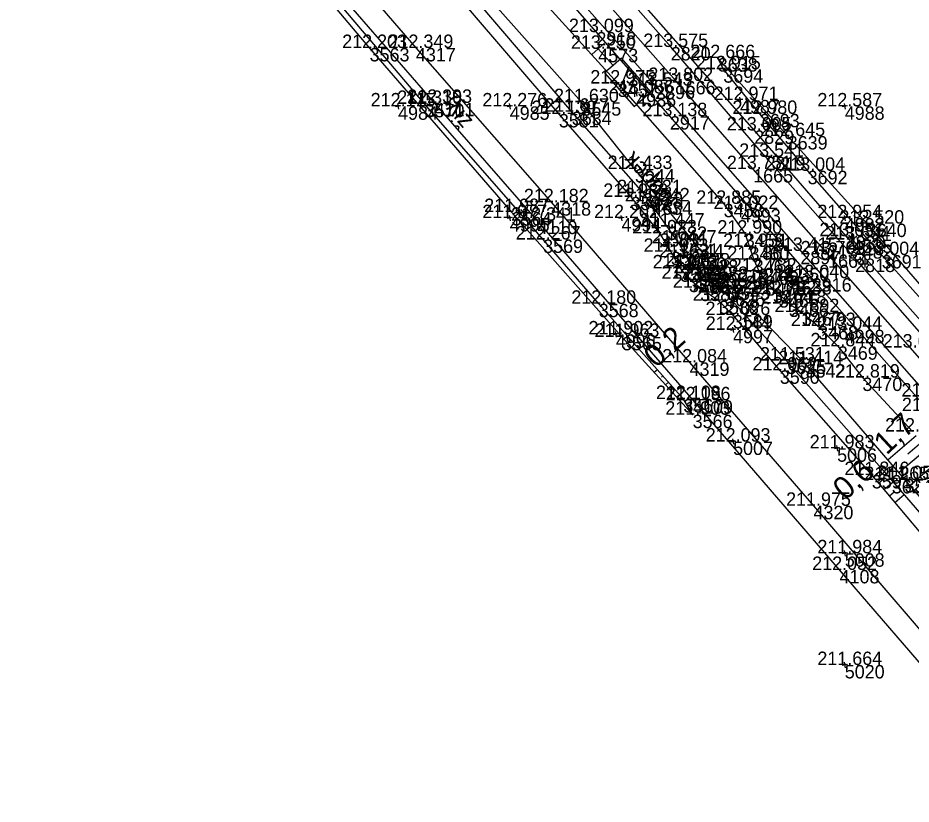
# Model space of a CAD drawing. Extents: x -556590 to -554855, y -1137918 to -1135717.
# Drawn here: x -555704 to -555624.1, y -1136522.5 to -1136452.1 of the extents above; entities that cross this region are included whole.
import ezdxf

# ---------------------------------------------------------------- set-up
doc = ezdxf.new("R2010")
doc.units = 0
for name, color, linetype in [('Vrstva 1', 7, 'Continuous'), ('Vrstva 4', 7, 'Continuous'), ('Vrstva 48', 7, 'Continuous'), ('Vrstva 49', 7, 'Continuous'), ('Vrstva 50', 7, 'Continuous'), ('Vrstva 51', 7, 'Continuous'), ('Vrstva 60', 7, 'Continuous'), ('Vrstva 61', 7, 'Continuous'), ('Vrstva 7', 7, 'Continuous')]:
    doc.layers.add(name, color=color, linetype=linetype)

msp = doc.modelspace()

# ---------------------------------------------------------------- linework, layer by layer
at = {"layer": 'Vrstva 1'}
msp.add_lwpolyline([(-555617.047, -1136489.655), (-555624.151, -1136481.584), (-555631.492, -1136473.245), (-555638.201, -1136465.612), (-555645.14, -1136457.724), (-555652.139, -1136449.756), (-555658.441, -1136442.59), (-555664.747, -1136435.415), (-555670.993, -1136428.307), (-555677.463, -1136420.947), (-555683.552, -1136414.017), (-555690.44, -1136406.179)], dxfattribs=at)
at = {"layer": 'Vrstva 4'}
for points in [[(-555622.431, -1136487.275), (-555632.955, -1136475.376), (-555645.659, -1136460.876), (-555652.243, -1136453.349), (-555664.779, -1136439.038), (-555675.055, -1136427.452), (-555687.678, -1136412.993), (-555700.952, -1136397.803)], [(-555697.757, -1136400.334), (-555685.919, -1136413.799), (-555674.147, -1136427.201), (-555663.818, -1136438.907), (-555656.688, -1136447.108), (-555646.98, -1136458.141), (-555633.977, -1136472.931), (-555622.465, -1136485.967)], [(-555620.12, -1136483.808), (-555629.064, -1136473.626), (-555637.092, -1136464.514), (-555645.582, -1136454.683), (-555654.149, -1136444.941), (-555659.148, -1136439.478), (-555660.228, -1136437.983), (-555660.506, -1136437.427), (-555660.012, -1136437.729), (-555658.962, -1136438.799), (-555656.562, -1136441.303), (-555649.119, -1136449.615), (-555638.104, -1136462.15), (-555629.912, -1136471.616), (-555620.889, -1136481.776)]]:
    msp.add_lwpolyline(points, dxfattribs=at)
at = {"layer": 'Vrstva 48'}
for p, q in [((-555646.783, -1136483.568), (-555647.059, -1136483.813)), ((-555646.285, -1136484.129), (-555646.42, -1136484.249)), ((-555645.787, -1136484.689), (-555646.05, -1136484.923)), ((-555645.289, -1136485.25), (-555645.417, -1136485.364)), ((-555644.791, -1136485.811), (-555645.04, -1136486.033)), ((-555623.6, -1136489.497), (-555626.11, -1136491.647)), ((-555622.624, -1136490.636), (-555625.131, -1136492.783)), ((-555623.112, -1136490.066), (-555624.366, -1136491.14)), ((-555621.649, -1136491.775), (-555624.149, -1136493.917)), ((-555627.452, -1136493.142), (-555626.648, -1136492.467)), ((-555626.97, -1136493.716), (-555626.56, -1136493.373)), ((-555626.487, -1136494.291), (-555625.656, -1136493.592)), ((-555626.004, -1136494.865), (-555625.584, -1136494.512)), ((-555625.522, -1136495.439), (-555624.673, -1136494.725))]:
    msp.add_line(p, q, dxfattribs=at)
at = {"layer": 'Vrstva 49'}
for p, q in [((-555648.424, -1136458.789), (-555648.916, -1136458.883)), ((-555648.717, -1136458.59), (-555648.623, -1136459.082)), ((-555639.135, -1136459.38), (-555639.627, -1136459.474)), ((-555639.428, -1136459.181), (-555639.334, -1136459.673)), ((-555669.754, -1136459.953), (-555670.246, -1136460.047)), ((-555670.047, -1136459.754), (-555669.953, -1136460.246)), ((-555659.754, -1136459.953), (-555660.246, -1136460.047)), ((-555660.047, -1136459.754), (-555659.953, -1136460.246)), ((-555629.754, -1136459.953), (-555630.246, -1136460.047)), ((-555630.047, -1136459.754), (-555629.953, -1136460.246)), ((-555639.055, -1136469.136), (-555639.547, -1136469.23)), ((-555639.348, -1136468.937), (-555639.254, -1136469.429)), ((-555659.754, -1136469.953), (-555660.246, -1136470.047)), ((-555660.047, -1136469.754), (-555659.953, -1136470.246)), ((-555649.754, -1136469.953), (-555650.246, -1136470.047)), ((-555650.047, -1136469.754), (-555649.953, -1136470.246)), ((-555629.754, -1136469.953), (-555630.246, -1136470.047)), ((-555630.047, -1136469.754), (-555629.953, -1136470.246)), ((-555650.259, -1136480.358), (-555650.751, -1136480.452)), ((-555650.552, -1136480.159), (-555650.458, -1136480.651)), ((-555639.754, -1136479.953), (-555640.246, -1136480.047)), ((-555640.047, -1136479.754), (-555639.953, -1136480.246)), ((-555629.754, -1136479.953), (-555630.246, -1136480.047)), ((-555630.047, -1136479.754), (-555629.953, -1136480.246)), ((-555639.754, -1136489.953), (-555640.246, -1136490.047)), ((-555640.047, -1136489.754), (-555639.953, -1136490.246)), ((-555630.44, -1136490.56), (-555630.932, -1136490.654)), ((-555630.733, -1136490.361), (-555630.639, -1136490.853)), ((-555629.754, -1136499.953), (-555630.246, -1136500.047)), ((-555630.047, -1136499.754), (-555629.953, -1136500.246)), ((-555629.754, -1136509.953), (-555630.246, -1136510.047)), ((-555630.047, -1136509.754), (-555629.953, -1136510.246))]:
    msp.add_line(p, q, dxfattribs=at)
for points in [[(-555615.08, -1136504.35), (-555624.636, -1136493.356), (-555633.501, -1136483.078), (-555640.265, -1136476.113), (-555648.785, -1136465.606), (-555653.585, -1136459.624), (-555664.726, -1136447.055), (-555673.42, -1136436.82), (-555678.151, -1136431.048), (-555682.973, -1136425.879), (-555688.067, -1136420.591), (-555689.304, -1136419.148), (-555693.118, -1136414.231), (-555703.25, -1136402.376)], [(-555643.618, -1136487.596), (-555644.451, -1136486.193), (-555652.029, -1136477.665), (-555657.009, -1136471.916), (-555667.622, -1136459.78), (-555677.531, -1136448.072), (-555681.376, -1136443.471), (-555688.944, -1136434.731), (-555696.701, -1136425.902), (-555705.857, -1136415.541), (-555707.805, -1136413.856)], [(-555707.805, -1136413.856), (-555701.555, -1136421.104), (-555693.021, -1136430.806), (-555681.957, -1136443.636), (-555672.551, -1136454.774), (-555659.833, -1136469.457), (-555649.952, -1136480.634), (-555643.618, -1136487.596)], [(-555679.234, -1136431.158), (-555677.752, -1136433.823), (-555673.144, -1136438.962), (-555668.881, -1136444.904), (-555664.096, -1136450.807), (-555655.601, -1136460.682), (-555649.17, -1136468.098), (-555646.587, -1136471.361), (-555645.564, -1136473.014), (-555644.747, -1136474.497), (-555643.95, -1136475.423), (-555642.94, -1136476.222), (-555641.262, -1136477.392), (-555640.019, -1136478.677), (-555635.816, -1136483.63), (-555627.575, -1136492.996), (-555620.189, -1136501.785)], [(-555619.626, -1136500.541), (-555625.788, -1136493.44), (-555635.233, -1136482.747), (-555640.706, -1136476.683), (-555642.014, -1136475.54), (-555642.886, -1136474.933), (-555643.62, -1136474.334), (-555644.179, -1136473.51), (-555644.832, -1136472.269), (-555645.899, -1136470.755), (-555648.036, -1136467.768), (-555654.446, -1136460.474), (-555665.404, -1136447.647), (-555672.407, -1136439.217), (-555677.696, -1136432.953), (-555679.234, -1136431.158)], [(-555658.834, -1136448.566), (-555650.327, -1136457.954), (-555640.841, -1136468.721), (-555638.953, -1136471.385), (-555638.53, -1136472.58), (-555638.155, -1136473.719), (-555637.666, -1136474.779), (-555637.082, -1136475.737), (-555636.426, -1136476.37), (-555635.902, -1136476.805), (-555634.995, -1136477.645), (-555633.841, -1136478.414), (-555632.374, -1136479.657), (-555630.619, -1136481.475), (-555628.42, -1136484.274), (-555623.94, -1136489.1)], [(-555621.141, -1136479.528), (-555626.686, -1136473.308), (-555633.32, -1136465.764), (-555637.605, -1136460.672), (-555640.872, -1136456.678), (-555641.373, -1136455.68)], [(-555641.373, -1136455.68), (-555635.108, -1136462.657), (-555628.029, -1136470.494), (-555620.784, -1136478.826)]]:
    msp.add_lwpolyline(points, dxfattribs=at)
at = {"layer": 'Vrstva 50'}
msp.add_line((-555647.289, -1136468.498), (-555647.189, -1136468.498), dxfattribs=at)
msp.add_circle((-555647.239, -1136468.498), 0.5, dxfattribs=at)
at = {"layer": 'Vrstva 51'}
for points in [[(-555743.133, -1136368.314), (-555733.406, -1136379.475), (-555727.162, -1136386.762), (-555718.214, -1136397.183), (-555709.998, -1136406.534), (-555700.89, -1136417.124), (-555690.385, -1136429.309), (-555680.58, -1136440.643), (-555668.402, -1136454.771), (-555656.288, -1136468.58), (-555643.895, -1136482.917), (-555632.798, -1136495.751), (-555617.483, -1136513.593), (-555605.979, -1136526.789), (-555593.57, -1136541.12), (-555579.464, -1136557.45), (-555567.58, -1136571.183), (-555555.68, -1136584.796), (-555545.666, -1136596.303), (-555537.365, -1136605.817), (-555530.457, -1136613.715), (-555520.191, -1136625.354), (-555507.504, -1136639.736)], [(-555505.522, -1136644.883), (-555519.562, -1136629.073), (-555531.744, -1136615.155), (-555540.175, -1136605.5), (-555547.673, -1136596.899), (-555556.471, -1136586.787), (-555567.721, -1136573.974), (-555575.942, -1136564.513), (-555582.917, -1136556.401), (-555594.357, -1136543.153), (-555603.925, -1136532.234), (-555617.682, -1136516.291), (-555630.463, -1136501.491), (-555643.583, -1136486.305), (-555657.513, -1136470.232), (-555666.727, -1136459.683), (-555678.561, -1136446.033), (-555691.372, -1136431.214), (-555703.054, -1136417.695), (-555713.773, -1136405.268), (-555725.819, -1136391.439), (-555738.306, -1136376.946), (-555744.231, -1136369.998)]]:
    msp.add_lwpolyline(points, dxfattribs=at)
at = {"layer": 'Vrstva 60'}
for p, q in [((-555652.243, -1136453.349), (-555652.243, -1136453.349)), ((-555672.551, -1136454.774), (-555672.551, -1136454.774)), ((-555668.402, -1136454.771), (-555668.402, -1136454.771)), ((-555645.582, -1136454.683), (-555645.582, -1136454.683)), ((-555652.073, -1136454.847), (-555652.073, -1136454.847)), ((-555641.373, -1136455.68), (-555641.373, -1136455.68)), ((-555640.872, -1136456.678), (-555640.872, -1136456.678)), ((-555650.327, -1136457.954), (-555650.327, -1136457.954)), ((-555645.14, -1136457.724), (-555645.14, -1136457.724)), ((-555646.98, -1136458.141), (-555646.98, -1136458.141)), ((-555653.585, -1136459.624), (-555653.585, -1136459.624)), ((-555648.67, -1136458.836), (-555648.67, -1136458.836)), ((-555639.381, -1136459.427), (-555639.381, -1136459.427)), ((-555670, -1136460), (-555670, -1136460)), ((-555667.622, -1136459.78), (-555667.622, -1136459.78)), ((-555666.727, -1136459.683), (-555666.727, -1136459.683)), ((-555660, -1136460), (-555660, -1136460)), ((-555630, -1136460), (-555630, -1136460)), ((-555655.601, -1136460.682), (-555655.601, -1136460.682)), ((-555654.446, -1136460.474), (-555654.446, -1136460.474)), ((-555645.659, -1136460.876), (-555645.659, -1136460.876)), ((-555637.605, -1136460.672), (-555637.605, -1136460.672)), ((-555638.104, -1136462.15), (-555638.104, -1136462.15)), ((-555635.108, -1136462.657), (-555635.108, -1136462.657)), ((-555637.092, -1136464.514), (-555637.092, -1136464.514)), ((-555648.785, -1136465.606), (-555648.785, -1136465.606)), ((-555638.201, -1136465.612), (-555638.201, -1136465.612)), ((-555633.32, -1136465.764), (-555633.32, -1136465.764)), ((-555649.17, -1136468.098), (-555649.17, -1136468.098)), ((-555648.036, -1136467.768), (-555648.036, -1136467.768)), ((-555656.288, -1136468.58), (-555656.288, -1136468.58)), ((-555647.239, -1136468.498), (-555647.239, -1136468.498)), ((-555640.841, -1136468.721), (-555640.841, -1136468.721)), ((-555639.301, -1136469.183), (-555639.301, -1136469.183)), ((-555660, -1136470), (-555660, -1136470)), ((-555659.833, -1136469.457), (-555659.833, -1136469.457)), ((-555650, -1136470), (-555650, -1136470)), ((-555630, -1136470), (-555630, -1136470)), ((-555657.513, -1136470.232), (-555657.513, -1136470.232)), ((-555645.899, -1136470.755), (-555645.899, -1136470.755)), ((-555628.029, -1136470.494), (-555628.029, -1136470.494)), ((-555646.587, -1136471.361), (-555646.587, -1136471.361)), ((-555638.953, -1136471.385), (-555638.953, -1136471.385)), ((-555629.912, -1136471.616), (-555629.912, -1136471.616)), ((-555657.009, -1136471.916), (-555657.009, -1136471.916)), ((-555644.832, -1136472.269), (-555644.832, -1136472.269)), ((-555629.296, -1136471.914), (-555629.296, -1136471.914)), ((-555645.564, -1136473.014), (-555645.564, -1136473.014)), ((-555638.53, -1136472.58), (-555638.53, -1136472.58)), ((-555633.977, -1136472.931), (-555633.977, -1136472.931)), ((-555644.179, -1136473.51), (-555644.179, -1136473.51)), ((-555638.155, -1136473.719), (-555638.155, -1136473.719)), ((-555631.492, -1136473.245), (-555631.492, -1136473.245)), ((-555629.064, -1136473.626), (-555629.064, -1136473.626)), ((-555626.686, -1136473.308), (-555626.686, -1136473.308)), ((-555644.747, -1136474.497), (-555644.747, -1136474.497)), ((-555643.62, -1136474.334), (-555643.62, -1136474.334)), ((-555637.666, -1136474.779), (-555637.666, -1136474.779)), ((-555643.95, -1136475.423), (-555643.95, -1136475.423)), ((-555642.886, -1136474.933), (-555642.886, -1136474.933)), ((-555642.014, -1136475.54), (-555642.014, -1136475.54)), ((-555632.955, -1136475.376), (-555632.955, -1136475.376)), ((-555642.94, -1136476.222), (-555642.94, -1136476.222)), ((-555640.265, -1136476.113), (-555640.265, -1136476.113)), ((-555637.082, -1136475.737), (-555637.082, -1136475.737)), ((-555636.426, -1136476.37), (-555636.426, -1136476.37)), ((-555634.74, -1136475.64), (-555634.74, -1136475.64)), ((-555640.706, -1136476.683), (-555640.706, -1136476.683)), ((-555635.902, -1136476.805), (-555635.902, -1136476.805)), ((-555652.029, -1136477.665), (-555652.029, -1136477.665)), ((-555641.262, -1136477.392), (-555641.262, -1136477.392)), ((-555634.995, -1136477.645), (-555634.995, -1136477.645)), ((-555640.019, -1136478.677), (-555640.019, -1136478.677)), ((-555633.841, -1136478.414), (-555633.841, -1136478.414)), ((-555650.505, -1136480.405), (-555650.505, -1136480.405)), ((-555640, -1136480), (-555640, -1136480)), ((-555632.374, -1136479.657), (-555632.374, -1136479.657)), ((-555630, -1136480), (-555630, -1136480)), ((-555649.952, -1136480.634), (-555649.952, -1136480.634)), ((-555630.619, -1136481.475), (-555630.619, -1136481.475)), ((-555624.151, -1136481.584), (-555624.151, -1136481.584)), ((-555635.233, -1136482.747), (-555635.233, -1136482.747)), ((-555643.895, -1136482.917), (-555643.895, -1136482.917)), ((-555633.501, -1136483.078), (-555633.501, -1136483.078)), ((-555635.816, -1136483.63), (-555635.816, -1136483.63)), ((-555628.42, -1136484.274), (-555628.42, -1136484.274)), ((-555644.451, -1136486.193), (-555644.451, -1136486.193)), ((-555643.583, -1136486.305), (-555643.583, -1136486.305)), ((-555643.618, -1136487.596), (-555643.618, -1136487.596)), ((-555640, -1136490), (-555640, -1136490)), ((-555630.686, -1136490.607), (-555630.686, -1136490.607)), ((-555627.575, -1136492.996), (-555627.575, -1136492.996)), ((-555625.788, -1136493.44), (-555625.788, -1136493.44)), ((-555624.636, -1136493.356), (-555624.636, -1136493.356)), ((-555632.798, -1136495.751), (-555632.798, -1136495.751)), ((-555630, -1136500), (-555630, -1136500)), ((-555630.463, -1136501.491), (-555630.463, -1136501.491)), ((-555630, -1136510), (-555630, -1136510))]:
    msp.add_line(p, q, dxfattribs=at)
at = {"layer": 'Vrstva 7'}
for p, q in [((-555651.51, -1136454.352), (-555652.636, -1136455.342)), ((-555649.342, -1136456.441), (-555650.185, -1136458.512)), ((-555649.525, -1136459.264), (-555648.682, -1136457.192)), ((-555629.671, -1136472.244), (-555628.921, -1136471.584)), ((-555628.966, -1136472.289), (-555629.626, -1136471.539)), ((-555634.69, -1136475.64), (-555634.79, -1136475.64))]:
    msp.add_line(p, q, dxfattribs=at)
msp.add_lwpolyline([(-555652.073, -1136454.847), (-555650.753, -1136456.35), (-555651.504, -1136457.01), (-555648.865, -1136460.015), (-555647.362, -1136458.695), (-555650.002, -1136455.69), (-555650.753, -1136456.35)], dxfattribs=at)
for centre, radius in [((-555631.72, -1136472.986), 0.75), ((-555634.74, -1136475.64), 0.5)]:
    msp.add_circle(centre, radius, dxfattribs=at)

# ---------------------------------------------------------------- texts
at = {"layer": 'Vrstva 48'}
for s, rotation, p in [('0,2', 41.62436, (-555646.898, -1136483.476)), ('1,7', 42.87071, (-555626.261, -1136491.261)), ('0,6', 41.45378, (-555629.965, -1136495.335))]:
    msp.add_text(s, height=2, rotation=rotation, dxfattribs=at).set_placement(p)
at = {"layer": 'Vrstva 50'}
msp.add_text('sloupek', height=1.5, rotation=131.33779, dxfattribs=at).set_placement((-555644.352, -1136469.115))
at = {"layer": 'Vrstva 51'}
msp.add_text('živ.', height=1.5, rotation=130.92397, dxfattribs=at).set_placement((-555663.271, -1136461.285))
at = {"layer": 'Vrstva 60'}
for s, p in [('2918', (-555652.243, -1136454.549)), ('3563', (-555672.551, -1136455.974)), ('4317', (-555668.402, -1136455.971)), ('4573', (-555652.073, -1136456.047)), ('2820', (-555645.582, -1136455.883)), ('3638', (-555641.373, -1136456.88)), ('3694', (-555640.872, -1136457.878)), ('3457', (-555650.327, -1136459.154)), ('1666', (-555645.14, -1136458.924)), ('4986', (-555648.67, -1136460.036)), ('2896', (-555646.98, -1136459.341)), ('3545', (-555653.585, -1136460.824)), ('4987', (-555639.381, -1136460.627)), ('4984', (-555670, -1136461.2)), ('3570', (-555667.622, -1136460.98)), ('4111', (-555666.727, -1136460.883)), ('4985', (-555660, -1136461.2)), ('4988', (-555630, -1136461.2)), ('3581', (-555655.601, -1136461.882)), ('3634', (-555654.446, -1136461.674)), ('2917', (-555645.659, -1136462.076)), ('3693', (-555637.605, -1136461.872)), ('2829', (-555638.104, -1136463.35)), ('3639', (-555635.108, -1136463.857)), ('2819', (-555637.092, -1136465.714)), ('3544', (-555648.785, -1136466.806)), ('1665', (-555638.201, -1136466.812)), ('3692', (-555633.32, -1136466.964)), ('3582', (-555649.17, -1136469.298)), ('3633', (-555648.036, -1136468.968)), ('4318', (-555656.288, -1136469.78)), ('4634', (-555647.239, -1136469.698)), ('3458', (-555640.841, -1136469.921)), ('4993', (-555639.301, -1136470.383)), ('4995', (-555660, -1136471.2)), ('3564', (-555659.833, -1136470.657)), ('4994', (-555650, -1136471.2)), ('4992', (-555630, -1136471.2)), ('4110', (-555657.513, -1136471.432)), ('3632', (-555645.899, -1136471.955)), ('3640', (-555628.029, -1136471.694)), ('3583', (-555646.587, -1136472.561)), ('3459', (-555638.953, -1136472.585)), ('2830', (-555629.912, -1136472.816)), ('3569', (-555657.009, -1136473.116)), ('3631', (-555644.832, -1136473.469)), ('4535', (-555629.296, -1136473.114)), ('3584', (-555645.564, -1136474.214)), ('3460', (-555638.53, -1136473.78)), ('2897', (-555633.977, -1136474.131)), ('1664', (-555631.492, -1136474.445)), ('3630', (-555644.179, -1136474.71)), ('3461', (-555638.155, -1136474.919)), ('2818', (-555629.064, -1136474.826)), ('3691', (-555626.686, -1136474.508)), ('3585', (-555644.747, -1136475.697)), ('3629', (-555643.62, -1136475.534)), ('3462', (-555637.666, -1136475.979)), ('3586', (-555643.95, -1136476.623)), ('3628', (-555642.886, -1136476.133)), ('3627', (-555642.014, -1136476.74)), ('1538', (-555634.74, -1136476.84)), ('2916', (-555632.955, -1136476.576)), ('3587', (-555642.94, -1136477.422)), ('3543', (-555640.265, -1136477.313)), ('3463', (-555637.082, -1136476.937)), ('3464', (-555636.426, -1136477.57)), ('3626', (-555640.706, -1136477.883)), ('3465', (-555635.902, -1136478.005)), ('3568', (-555652.029, -1136478.865)), ('3588', (-555641.262, -1136478.592)), ('3466', (-555634.995, -1136478.845)), ('3589', (-555640.019, -1136479.877)), ('3467', (-555633.841, -1136479.614)), ('4996', (-555650.505, -1136481.605)), ('4997', (-555640, -1136481.2)), ('3468', (-555632.374, -1136480.857)), ('4998', (-555630, -1136481.2)), ('3565', (-555649.952, -1136481.834)), ('3469', (-555630.619, -1136482.675)), ('3625', (-555635.233, -1136483.947)), ('4319', (-555643.895, -1136484.117)), ('3590', (-555635.816, -1136484.83)), ('3542', (-555633.501, -1136484.278)), ('3470', (-555628.42, -1136485.474)), ('3567', (-555644.451, -1136487.393)), ('4109', (-555643.583, -1136487.505)), ('3566', (-555643.618, -1136488.796)), ('5007', (-555640, -1136491.2)), ('5006', (-555630.686, -1136491.807)), ('3591', (-555627.575, -1136494.196)), ('3624', (-555625.788, -1136494.64)), ('3541', (-555624.636, -1136494.556)), ('4320', (-555632.798, -1136496.951)), ('5008', (-555630, -1136501.2)), ('4108', (-555630.463, -1136502.691)), ('5020', (-555630, -1136511.2))]:
    msp.add_text(s, height=1.2, dxfattribs=at).set_placement(p)
at = {"layer": 'Vrstva 61'}
for s, p in [('213.099', (-555654.697, -1136453.349)), ('212.203', (-555675.003, -1136454.774)), ('212.349', (-555670.856, -1136454.771)), ('213.250', (-555654.524, -1136454.847)), ('213.575', (-555648.038, -1136454.683)), ('212.666', (-555643.825, -1136455.68)), ('212.915', (-555643.328, -1136456.678)), ('212.975', (-555652.783, -1136457.954)), ('213.543', (-555649.432, -1136458.141)), ('213.802', (-555647.588, -1136457.724)), ('213.086', (-555651.122, -1136458.836)), ('212.115', (-555672.456, -1136460)), ('212.316', (-555670.074, -1136459.78)), ('212.393', (-555669.179, -1136459.683)), ('212.276', (-555662.452, -1136460)), ('211.630', (-555656.036, -1136459.624)), ('212.971', (-555641.738, -1136459.427)), ('212.587', (-555632.452, -1136460)), ('212.139', (-555658.055, -1136460.682)), ('211.677', (-555656.898, -1136460.474)), ('212.980', (-555640.056, -1136460.672)), ('213.138', (-555648.113, -1136460.876)), ('213.005', (-555640.56, -1136462.15)), ('212.645', (-555637.564, -1136462.657)), ('213.541', (-555639.449, -1136464.514)), ('211.433', (-555651.237, -1136465.606)), ('213.751', (-555640.558, -1136465.612)), ('213.004', (-555635.771, -1136465.764)), ('211.531', (-555650.393, -1136467.768)), ('212.182', (-555658.736, -1136468.58)), ('211.983', (-555651.622, -1136468.098)), ('211.542', (-555649.687, -1136468.498)), ('212.885', (-555643.297, -1136468.721)), ('211.987', (-555662.285, -1136469.457)), ('213.022', (-555641.749, -1136469.183)), ('211.977', (-555662.452, -1136470)), ('212.341', (-555659.87, -1136470.232)), ('212.202', (-555652.448, -1136470)), ('212.954', (-555632.451, -1136470)), ('211.447', (-555648.351, -1136470.755)), ('212.520', (-555630.48, -1136470.494)), ('212.267', (-555659.461, -1136471.916)), ('211.923', (-555649.039, -1136471.361)), ('212.990', (-555641.404, -1136471.385)), ('213.051', (-555632.269, -1136471.616)), ('213.694', (-555631.747, -1136471.914)), ('211.447', (-555647.284, -1136472.269)), ('212.951', (-555640.887, -1136472.58)), ('211.923', (-555648.016, -1136473.014)), ('211.544', (-555646.63, -1136473.51)), ('213.415', (-555636.433, -1136472.931)), ('213.705', (-555633.948, -1136473.245)), ('213.482', (-555631.512, -1136473.626)), ('213.004', (-555629.137, -1136473.308)), ('211.628', (-555646.074, -1136474.334)), ('212.861', (-555640.512, -1136473.719)), ('211.923', (-555647.199, -1136474.497)), ('211.628', (-555645.34, -1136474.933)), ('212.782', (-555640.114, -1136474.779)), ('212.029', (-555646.404, -1136475.423)), ('211.628', (-555644.468, -1136475.54)), ('212.782', (-555639.53, -1136475.737)), ('213.350', (-555637.191, -1136475.64)), ('213.040', (-555635.406, -1136475.376)), ('212.029', (-555645.394, -1136476.222)), ('211.628', (-555643.16, -1136476.683)), ('211.545', (-555642.721, -1136476.113)), ('212.782', (-555638.874, -1136476.37)), ('212.782', (-555638.35, -1136476.805)), ('212.051', (-555643.619, -1136477.392)), ('212.718', (-555637.449, -1136477.645)), ('212.180', (-555654.48, -1136477.665)), ('212.692', (-555636.289, -1136478.414)), ('212.026', (-555642.471, -1136478.677)), ('212.144', (-555642.451, -1136480)), ('212.793', (-555634.826, -1136479.657)), ('213.044', (-555632.451, -1136480)), ('211.902', (-555652.953, -1136480.405)), ('211.963', (-555652.404, -1136480.634)), ('212.844', (-555633.07, -1136481.475)), ('213.664', (-555626.602, -1136481.584)), ('212.084', (-555646.346, -1136482.917)), ('211.531', (-555637.59, -1136482.747)), ('211.414', (-555635.952, -1136483.078)), ('212.062', (-555638.264, -1136483.63)), ('212.819', (-555630.874, -1136484.274)), ('212.108', (-555646.905, -1136486.193)), ('212.196', (-555646.035, -1136486.305)), ('213.338', (-555624.919, -1136485.967)), ('211.903', (-555646.07, -1136487.596)), ('213.003', (-555624.883, -1136487.275)), ('212.820', (-555626.391, -1136489.1)), ('212.093', (-555642.452, -1136490)), ('211.983', (-555633.138, -1136490.607)), ('211.846', (-555630.027, -1136492.996)), ('211.265', (-555628.244, -1136493.44)), ('211.054', (-555627.087, -1136493.356)), ('211.975', (-555635.254, -1136495.751)), ('211.984', (-555632.451, -1136500)), ('212.052', (-555632.911, -1136501.491)), ('211.664', (-555632.451, -1136510))]:
    msp.add_text(s, height=1.2, dxfattribs=at).set_placement(p)

doc.saveas('drawing.dxf')
